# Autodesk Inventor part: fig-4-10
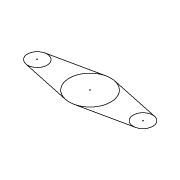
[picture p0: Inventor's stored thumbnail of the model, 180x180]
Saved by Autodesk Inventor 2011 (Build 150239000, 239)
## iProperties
Created: 2005-02
Part Number: fig-4-10
Document SubType Name: Modeling
Designer: CADCIM
Manufacturer: Standard
Standards Organization: Custom
Density: 1 g/cm^3
Author: CADCIM
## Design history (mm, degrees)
sketch "Sketch1"
  geometry: L1 (-33.874, 5.844)-(-2.722, 12.469); L2 (2.595, 12.472)-(33.871, 5.852); L3 (-33.884, -5.902)-(-2.745, -12.585); L4 (2.595, -12.592)-(33.871, -5.972); A1 r 12.81 centre (-0.057, -0.06) between (-2.722, 12.469) and (2.595, 12.472); A2 r 6.006 centre (-32.624, -0.03) between (-33.874, 5.844) and (-33.884, -5.902); A3 r 6.043 centre (32.619, -0.06) between (33.871, 5.852) and (33.871, -5.972)
  constraints: 8 end point, 8 point on circle, 8 tangent, 3 centre point, 1 other
